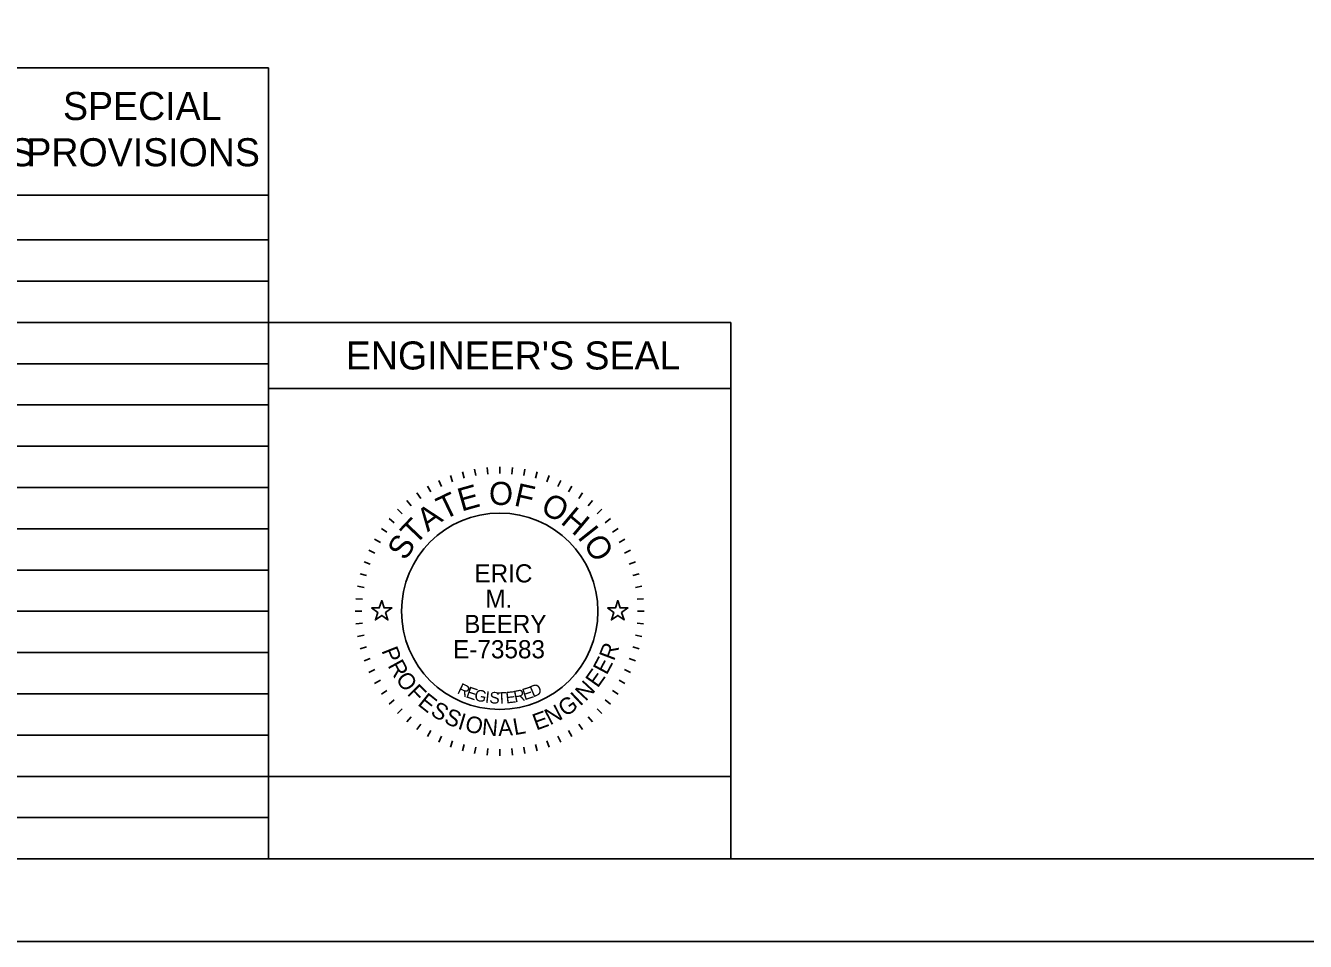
# Model space of a CAD drawing. Extents: x 0 to 34, y 0 to 22.
# Drawn here: x 22.13 to 29.88, y 0 to 5.55 of the extents above; entities that cross this region are included whole.
import ezdxf

# ---------------------------------------------------------------- set-up
doc = ezdxf.new("R2010")
doc.units = 0
for name, color, linetype in [('Default', 7, 'Continuous'), ('SH_Border', 7, 'Continuous'), ('SH_Cut_Line', 7, 'Continuous'), ('SH_Data', 7, 'Continuous'), ('SH_Text', 7, 'Continuous')]:
    doc.layers.add(name, color=color, linetype=linetype)

msp = doc.modelspace()

# ---------------------------------------------------------------- linework, layer by layer
at = {"layer": 'Default'}
for points in [[(24.2236, 2.02), (24.2705, 2.02), (24.285, 2.0645), (24.2995, 2.02), (24.3464, 2.02), (24.3085, 1.9924), (24.323, 1.9478), (24.285, 1.9754), (24.247, 1.9478), (24.2615, 1.9924)], [(25.6536, 2.02), (25.7005, 2.02), (25.715, 2.0645), (25.7295, 2.02), (25.7764, 2.02), (25.7385, 1.9924), (25.753, 1.9478), (25.715, 1.9754), (25.677, 1.9478), (25.6915, 1.9924)]]:
    msp.add_lwpolyline(points, close=True, dxfattribs=at)
at = {"layer": 'SH_Border'}
msp.add_lwpolyline([(1.5, 21.5), (33.5, 21.5), (33.5, 0.5), (1.5, 0.5)], close=True, dxfattribs=at)
at = {"layer": 'SH_Cut_Line'}
msp.add_lwpolyline([(0, 0), (34, 0), (34, 22), (0, 22)], close=True, dxfattribs=at)
at = {"layer": 'SH_Data'}
for p, q in [((10.15, 5.2917), (23.6, 5.2917)), ((23.6, 0.5), (23.6, 5.2917)), ((10.15, 4.5209), (23.6, 4.5209)), ((10.15, 4.25), (23.6, 4.25)), ((10.15, 4), (23.6, 4)), ((10.15, 3.75), (23.6, 3.75)), ((23.6, 0.5), (23.6, 3.75)), ((23.6, 3.75), (26.4, 3.75)), ((26.4, 3.75), (26.4, 0.5)), ((10.15, 3.5), (23.6, 3.5)), ((23.6, 3.35), (26.4, 3.35)), ((10.15, 3.25), (23.6, 3.25)), ((10.15, 3), (23.6, 3)), ((24.9237, 2.8717), (24.9272, 2.8318)), ((25, 2.875), (25, 2.835)), ((25.0763, 2.8717), (25.0728, 2.8318)), ((24.6302, 2.793), (24.6471, 2.7568)), ((24.7007, 2.8222), (24.7144, 2.7846)), ((24.7735, 2.8452), (24.7839, 2.8065)), ((24.8481, 2.8617), (24.855, 2.8223)), ((25.1519, 2.8617), (25.145, 2.8223)), ((25.2265, 2.8452), (25.2161, 2.8065)), ((25.2993, 2.8222), (25.2856, 2.7846)), ((25.3698, 2.793), (25.3529, 2.7568)), ((10.15, 2.75), (23.6, 2.75)), ((24.4981, 2.7168), (24.5211, 2.684)), ((24.5625, 2.7578), (24.5825, 2.7231)), ((25.4375, 2.7578), (25.4175, 2.7231)), ((25.5019, 2.7168), (25.4789, 2.684)), ((24.4376, 2.6703), (24.4633, 2.6396)), ((25.5624, 2.6703), (25.5367, 2.6396)), ((24.3297, 2.5624), (24.3604, 2.5367)), ((24.3813, 2.6187), (24.4096, 2.5904)), ((25.6187, 2.6187), (25.5904, 2.5904)), ((25.6703, 2.5624), (25.6396, 2.5367)), ((10.15, 2.5), (23.6, 2.5)), ((24.2832, 2.5019), (24.316, 2.4789)), ((25.7168, 2.5019), (25.684, 2.4789)), ((24.2422, 2.4375), (24.2769, 2.4175)), ((25.7578, 2.4375), (25.7231, 2.4175)), ((24.207, 2.3698), (24.2432, 2.3529)), ((25.793, 2.3698), (25.7568, 2.3529)), ((10.15, 2.25), (23.6, 2.25)), ((24.1778, 2.2993), (24.2154, 2.2856)), ((25.8222, 2.2993), (25.7846, 2.2856)), ((24.1548, 2.2265), (24.1935, 2.2161)), ((25.8452, 2.2265), (25.8065, 2.2161)), ((24.1383, 2.1519), (24.1777, 2.145)), ((25.8617, 2.1519), (25.8223, 2.145)), ((24.1283, 2.0763), (24.1682, 2.0728)), ((25.8717, 2.0763), (25.8318, 2.0728)), ((10.15, 2), (23.6, 2)), ((24.125, 2), (24.165, 2)), ((25.875, 2), (25.835, 2)), ((24.1283, 1.9237), (24.1682, 1.9272)), ((25.8717, 1.9237), (25.8318, 1.9272)), ((24.1383, 1.8481), (24.1777, 1.855)), ((24.1548, 1.7735), (24.1935, 1.7839)), ((25.8452, 1.7735), (25.8065, 1.7839)), ((25.8617, 1.8481), (25.8223, 1.855)), ((10.15, 1.75), (23.6, 1.75)), ((24.1778, 1.7007), (24.2154, 1.7144)), ((25.8222, 1.7007), (25.7846, 1.7144)), ((24.207, 1.6302), (24.2432, 1.6471)), ((25.793, 1.6302), (25.7568, 1.6471)), ((24.2422, 1.5625), (24.2769, 1.5825)), ((25.7578, 1.5625), (25.7231, 1.5825)), ((10.15, 1.5), (23.6, 1.5)), ((24.2832, 1.4981), (24.316, 1.5211)), ((25.7168, 1.4981), (25.684, 1.5211)), ((24.3297, 1.4376), (24.3604, 1.4633)), ((24.3813, 1.3813), (24.4096, 1.4096)), ((25.6187, 1.3813), (25.5904, 1.4096)), ((25.6703, 1.4376), (25.6396, 1.4633)), ((24.4376, 1.3297), (24.4633, 1.3604)), ((25.5624, 1.3297), (25.5367, 1.3604)), ((10.15, 1.25), (23.6, 1.25)), ((24.4981, 1.2832), (24.5211, 1.316)), ((24.5625, 1.2422), (24.5825, 1.2769)), ((24.6302, 1.207), (24.6471, 1.2432)), ((25.3698, 1.207), (25.3529, 1.2432)), ((25.4375, 1.2422), (25.4175, 1.2769)), ((25.5019, 1.2832), (25.4789, 1.316)), ((24.7007, 1.1778), (24.7144, 1.2154)), ((24.7735, 1.1548), (24.7839, 1.1935)), ((24.8481, 1.1383), (24.855, 1.1777)), ((24.9237, 1.1283), (24.9272, 1.1682)), ((25, 1.125), (25, 1.165)), ((25.0763, 1.1283), (25.0728, 1.1682)), ((25.1519, 1.1383), (25.145, 1.1777)), ((25.2265, 1.1548), (25.2161, 1.1935)), ((25.2993, 1.1778), (25.2856, 1.2154)), ((10.15, 1), (23.6, 1)), ((10.15, 0.75), (23.6, 0.75)), ((23.6, 0.5), (26.4, 0.5))]:
    msp.add_line(p, q, dxfattribs=at)
msp.add_lwpolyline([(23.6, 0.5), (23.6, 1), (26.4, 1), (26.4, 0.5)], close=True, dxfattribs=at)
msp.add_circle((25, 2), 0.595, dxfattribs=at)

# ---------------------------------------------------------------- texts
for s, height, p in [("ENGINEER'S SEAL", 0.17, (24.0676, 3.465)), ('ERIC', 0.11, (24.8465, 2.1749)), ('M.', 0.11, (24.9126, 2.0216)), ('BEERY', 0.11, (24.7848, 1.8684)), ('E-73583', 0.11, (24.7177, 1.7151))]:
    msp.add_text(s, height=height, dxfattribs=at).set_placement(p)
for s, height, rotation, p in [('T', 0.14, 25.71674, (24.6616, 2.5518)), ('E', 0.14, 15.75706, (24.7684, 2.6038)), ('O', 0.14, 359.78119, (24.9347, 2.6443)), ('F', 0.14, 347.43619, (25.0811, 2.6417)), ('O', 0.14, 332.25863, (25.2398, 2.6015)), ('T', 0.14, 46.4344, (24.4883, 2.3964)), ('A', 0.14, 36.47472, (24.5634, 2.4781)), ('H', 0.14, 319.91363, (25.3632, 2.5361)), ('I', 0.14, 308.36695, (25.4665, 2.4483)), ('S', 0.14, 57.19238, (24.4281, 2.3014)), ('O', 0.14, 303.14906, (25.5021, 2.4089)), ('P', 0.1, 291.49398, (24.2823, 1.7621)), ('R', 0.1, 69.23216, (25.6919, 1.6954)), ('R', 0.1, 298.73106, (24.319, 1.6717)), ('E', 0.1, 61.99508, (25.6476, 1.6098)), ('E', 0.1, 54.75801, (25.5933, 1.5314)), ('O', 0.1, 306.46664, (24.3655, 1.5883)), ('F', 0.1, 314.7068, (24.4343, 1.4983)), ('R', 0.07, 334.48695, (24.7375, 1.5051)), ('D', 0.07, 23.30524, (25.201, 1.477)), ('N', 0.1, 47.02243, (25.5202, 1.4508)), ('E', 0.1, 321.43929, (24.4978, 1.4348)), ('E', 0.07, 341.03996, (24.7906, 1.4801)), ('G', 0.07, 347.47515, (24.8414, 1.4618)), ('I', 0.07, 353.78581, (24.9091, 1.4468)), ('S', 0.07, 356.89262, (24.9358, 1.4429)), ('T', 0.07, 3.00609, (24.9857, 1.4387)), ('E', 0.07, 6.01169, (25.0389, 1.4412)), ('R', 0.07, 11.91844, (25.0925, 1.4474)), ('E', 0.07, 17.68363, (25.1498, 1.4602)), ('G', 0.1, 35.04687, (25.3981, 1.357)), ('I', 0.1, 43.28703, (25.4868, 1.4214)), ('S', 0.1, 328.67637, (24.5743, 1.3752)), ('S', 0.1, 335.91345, (24.6564, 1.3266)), ('E', 0.1, 20.07421, (25.2212, 1.277)), ('N', 0.1, 27.31129, (25.3045, 1.3075)), ('I', 0.1, 343.15053, (24.7406, 1.2897)), ('O', 0.1, 346.88592, (24.7839, 1.2751)), ('N', 0.1, 355.12608, (24.8888, 1.2517)), ('A', 0.1, 2.86166, (24.9923, 1.2437)), ('L', 0.1, 10.09874, (25.0894, 1.249))]:
    msp.add_text(s, height=height, rotation=rotation, dxfattribs=at).set_placement(p)
at = {"layer": 'SH_Text'}
for s, p in [('SPECIAL', (22.3542, 4.9763)), ('SPECIFICATIONS', (20.2871, 4.6963)), ('PROVISIONS', (22.1323, 4.6963))]:
    msp.add_text(s, height=0.17, dxfattribs=at).set_placement(p)

doc.saveas('drawing.dxf')
